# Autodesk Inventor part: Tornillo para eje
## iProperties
Shininess: 64.0
Length Units: 11272
Angle Units: 11279
Time Units: 11290
Mass Units: 11286
Length Display Precision: 3
Angle Display Precision: 2
Compacted: True
Part Number: Tornillo para eje
Document SubType Name: Modeling
Created: 2005-06
Designer: alek
Manufacturer: Standard
Standards Organization: Custom
Density: 0.0
Volumn: 0.0
Area: 0.0
PropertySet Name: Model Information
Control State: 0
Master: False
Checked Out: False
Author: alek
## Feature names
1. Revolution1
2. Extrusion2
